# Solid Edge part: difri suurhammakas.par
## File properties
Author: Türk
Template: Iso Part.par
Last saved by: Türk
Revision: 25
Application: Solid Edge
Accuracy: 0,990
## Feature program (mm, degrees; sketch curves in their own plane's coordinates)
pattern "PatternOccurrence_2"  XOffset = 5.5385 deg
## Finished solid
Body 1: solid body, 425 faces, 988 edges, 560 vertices.
  Faces by surface: plane 343, cone 70, cylinder 12
  Edges by curve: line 556, circle 292, intersection 140
Bounding box of the edges (mm): 199.980 x 170.000 x 200.000, from (-99.9803, -70, -100) to (100, 100, 100).
Cylindrical faces by radius (mm): R7.5 x2, R40 x2, R50 x3, R60 x4, R95.0133 x1
Conical faces (half-angle, radius in mm at the cone's reference point): 45 deg R50 x3, 45 deg R60 x2, 45 deg R80 x65
Planar faces by outward normal: +x 1, +y 71, +z 2, -x 1, -y 71, -z 2, oblique 195
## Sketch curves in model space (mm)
line (-35, 50, 0) -> (-35, -20, 0)
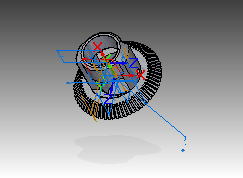
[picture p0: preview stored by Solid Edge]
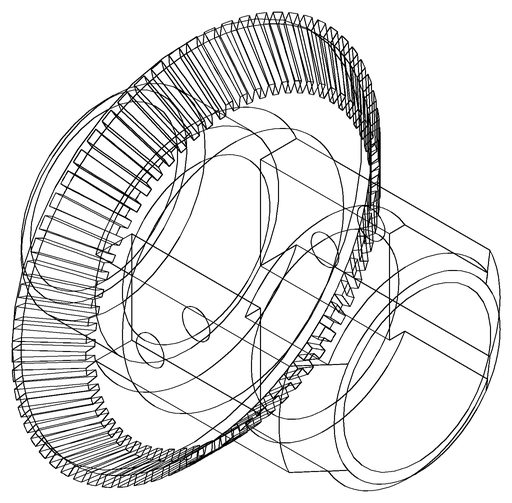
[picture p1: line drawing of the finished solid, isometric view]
